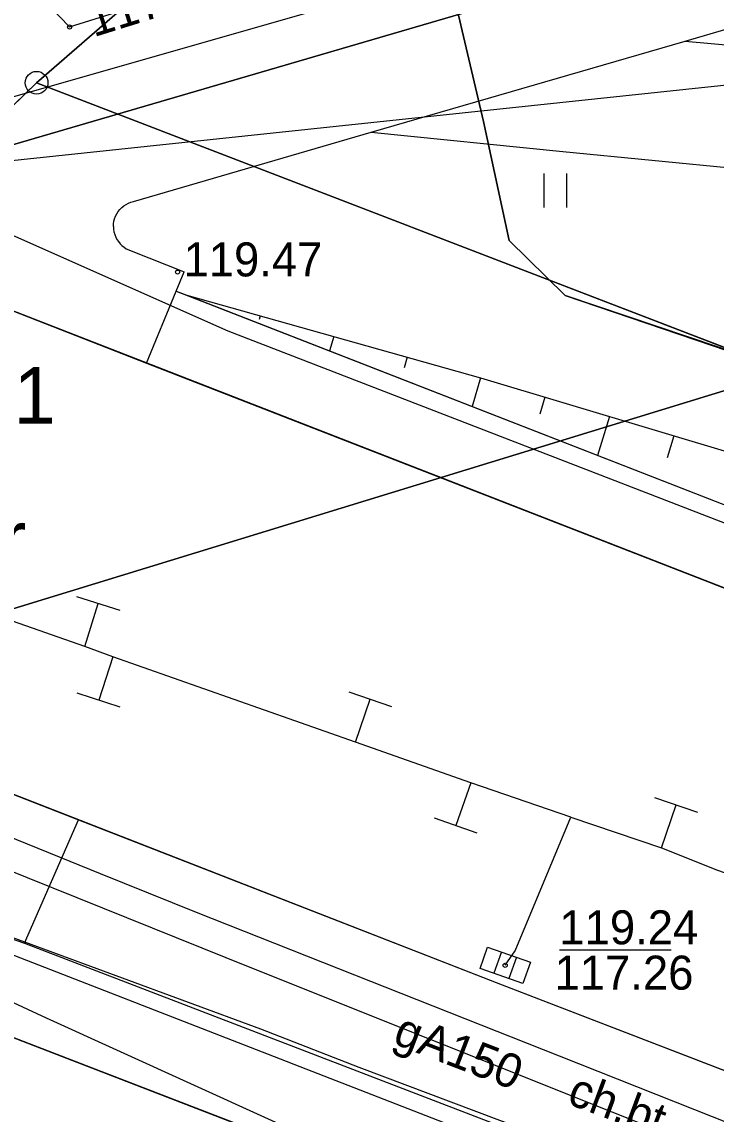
# Model space of a CAD drawing. Extents: x 6432121 to 6432331, y 5662538 to 5662686.
# Drawn here: x 6432164.01 to 6432179.34, y 5662599.43 to 5662623.53 of the extents above; entities that cross this region are included whole.
import ezdxf

# ---------------------------------------------------------------- set-up
doc = ezdxf.new("R2010")
doc.units = 0
for name, color, linetype in [('Warstwa 1', 7, 'Continuous'), ('Warstwa 10', 7, 'Continuous'), ('Warstwa 12', 7, 'Continuous'), ('Warstwa 13', 7, 'Continuous'), ('Warstwa 14', 7, 'Continuous'), ('Warstwa 15', 7, 'Continuous'), ('Warstwa 19', 7, 'Continuous'), ('Warstwa 2', 7, 'Continuous'), ('Warstwa 20', 7, 'Continuous'), ('Warstwa 21', 7, 'Continuous'), ('Warstwa 25', 7, 'Continuous'), ('Warstwa 4', 7, 'Continuous'), ('Warstwa 5', 7, 'Continuous'), ('Warstwa 6', 7, 'Continuous'), ('Warstwa 8', 7, 'Continuous'), ('Warstwa 9', 7, 'Continuous')]:
    doc.layers.add(name, color=color, linetype=linetype)

msp = doc.modelspace()

# ---------------------------------------------------------------- linework, layer by layer
at = {"layer": 'Warstwa 1'}
for p, q in [((6432164.332, 5662622.19), (6432166.394, 5662623.975)), ((6432164.332, 5662622.19), (6432166.394, 5662623.975)), ((6432147.05, 5662605.45), (6432164.332, 5662622.19)), ((6432147.05, 5662605.45), (6432164.332, 5662622.19)), ((6432164.332, 5662622.19), (6432180.9, 5662615.82)), ((6432164.332, 5662622.19), (6432180.9, 5662615.82)), ((6432147.05, 5662605.45), (6432180.9, 5662615.82)), ((6432147.05, 5662605.45), (6432180.9, 5662615.82)), ((6432155.186, 5662604.45), (6432246.621, 5662569.177)), ((6432155.186, 5662604.45), (6432246.621, 5662569.177))]:
    msp.add_line(p, q, dxfattribs=at)
at = {"layer": 'Warstwa 10'}
for p, q in [((6432167.648, 5662617.501), (6432174.135, 5662615.678)), ((6432167.648, 5662617.501), (6432210.732, 5662600.706)), ((6432169.27, 5662617.045), (6432169.248, 5662616.966)), ((6432170.892, 5662616.59), (6432170.802, 5662616.272)), ((6432172.514, 5662616.134), (6432172.446, 5662615.896)), ((6432174.135, 5662615.678), (6432173.951, 5662615.044)), ((6432174.135, 5662615.678), (6432199.73, 5662608.02)), ((6432175.557, 5662615.253), (6432175.446, 5662614.878)), ((6432176.979, 5662614.828), (6432176.72, 5662613.965)), ((6432178.401, 5662614.402), (6432178.254, 5662613.913))]:
    msp.add_line(p, q, dxfattribs=at)
msp.add_circle((6432164.332, 5662622.19), 0.25, dxfattribs=at)
at = {"layer": 'Warstwa 12'}
for points in [[(6432151.934, 5662659.962), (6432163.647, 5662662.364), (6432165.031, 5662661.271), (6432166.026, 5662656.887), (6432167.998, 5662648.227), (6432170.198, 5662638.637), (6432172.215, 5662629.789), (6432174.2, 5662621.336), (6432174.764, 5662618.709), (6432176.004, 5662617.499), (6432181.388, 5662615.664), (6432187.493, 5662613.63), (6432194.563, 5662611.29), (6432209.024, 5662605.561), (6432218.668, 5662601.72), (6432230.17, 5662597.186), (6432236.4, 5662594.702), (6432238.551, 5662593.742), (6432242.89, 5662591.993), (6432244.915, 5662591.158), (6432249.823, 5662589.199), (6432255.518, 5662586.99), (6432264.175, 5662583.483)], [(6432246.73, 5662630.84), (6432246.66, 5662631.45), (6432245.74, 5662640.67), (6432245.267, 5662641.347), (6432244.6, 5662641.33), (6432196.62, 5662630.41), (6432162.36, 5662620.4), (6432161.76, 5662619.96), (6432161.08, 5662620.39), (6432144.64, 5662638.75), (6432139.05, 5662643.99), (6432134.66, 5662649.12), (6432133.76, 5662650.98), (6432133.196, 5662651.358)], [(6432157.15, 5662630.3), (6432157.97, 5662630.56), (6432158.44, 5662630.26), (6432165.06, 5662623.42), (6432193.45, 5662632.27), (6432200.21, 5662630.55), (6432202.99, 5662631.34), (6432212.51, 5662634.26), (6432214.29, 5662637.14), (6432238.97, 5662644.59), (6432245.32, 5662646.8), (6432246.36, 5662647.14)], [(6432161.76, 5662619.96), (6432162.36, 5662620.4), (6432196.62, 5662630.41), (6432244.6, 5662641.33), (6432245.267, 5662641.347)], [(6432156.818, 5662630.202), (6432158.039, 5662625.384), (6432159.105, 5662620.911), (6432168.554, 5662616.714), (6432182.01, 5662611.519), (6432201.034, 5662604.23), (6432217.284, 5662598.028), (6432236.124, 5662590.737), (6432242.639, 5662588.267), (6432252.12, 5662584.559), (6432258.988, 5662581.806), (6432263.17, 5662580.184), (6432269.496, 5662577.686)], [(6432244.915, 5662591.158), (6432242.89, 5662591.993), (6432238.551, 5662593.742), (6432237.475, 5662594.222), (6432236.4, 5662594.702), (6432230.17, 5662597.186), (6432224.419, 5662599.453), (6432218.668, 5662601.72), (6432209.024, 5662605.561), (6432194.563, 5662611.29), (6432187.493, 5662613.63), (6432176.004, 5662617.499), (6432174.764, 5662618.709), (6432174.2, 5662621.336), (6432172.215, 5662629.789)], [(6432249.05, 5662629.25), (6432248.64, 5662629.45), (6432162.596, 5662620.344), (6432161.76, 5662619.96)], [(6432210.104, 5662582.327), (6432202.024, 5662585.528), (6432196.52, 5662587.717), (6432191.249, 5662589.791), (6432189.37, 5662590.565), (6432183.794, 5662592.014), (6432184.035, 5662592.662), (6432182.021, 5662593.597), (6432173.569, 5662597.514), (6432171.087, 5662598.578), (6432164.548, 5662601.548), (6432162.154, 5662602.662), (6432161.25, 5662603.009), (6432157.524, 5662604.493), (6432155.401, 5662604.519), (6432154.521, 5662606.358), (6432156.966, 5662612.242), (6432159.458, 5662618.215), (6432160.518, 5662620.909), (6432160.428, 5662620.978), (6432157.66, 5662622.108), (6432158.701, 5662622.869), (6432165.926, 5662625.245)], [(6432127.185, 5662618.897), (6432135.629, 5662615.848), (6432142.79, 5662613.281), (6432154.997, 5662608.849), (6432160.46, 5662606.879), (6432165.736, 5662604.745), (6432167.852, 5662603.89), (6432175.869, 5662600.716), (6432188.607, 5662595.673), (6432197.141, 5662592.258), (6432208.285, 5662587.853), (6432217.328, 5662584.25), (6432226.269, 5662580.703), (6432229.116, 5662579.575), (6432234.631, 5662577.404), (6432234.076, 5662575.247), (6432232.817, 5662570.334), (6432230.472, 5662561.671), (6432228.926, 5662556.053)], [(6432228.367, 5662556.053), (6432231.658, 5662568.249), (6432233.96, 5662576.659), (6432221.597, 5662581.652), (6432210.31, 5662586.256), (6432196.752, 5662591.605), (6432184.96, 5662596.314), (6432169.081, 5662602.651), (6432160.264, 5662606.196), (6432148.936, 5662610.33), (6432147.827, 5662610.792), (6432135.842, 5662615.166), (6432127.959, 5662618.065)], [(6432127.946, 5662615.962), (6432128.842, 5662616.521), (6432129.879, 5662616.161), (6432135.004, 5662614.244), (6432137.96, 5662613.1), (6432142.879, 5662611.278), (6432154.141, 5662607.021), (6432159.281, 5662605.095), (6432161.845, 5662604.079), (6432162.876, 5662603.668), (6432169.279, 5662601.311), (6432171.448, 5662600.465), (6432177.657, 5662598.132), (6432182.74, 5662596.197), (6432190.963, 5662593.097), (6432191.954, 5662592.706)], [(6432176.128, 5662605.986), (6432173.923, 5662606.743), (6432171.375, 5662607.643), (6432166.013, 5662609.519), (6432165.395, 5662609.747), (6432160.301, 5662611.534), (6432159.028, 5662611.977)], [(6432125.976, 5662559.881), (6432127.22, 5662563.81), (6432133.93, 5662584.09), (6432142.61, 5662608.19), (6432143.204, 5662608.85), (6432144.41, 5662608.72), (6432156.66, 5662605.17), (6432161.55, 5662603.82), (6432185, 5662594.71), (6432189.43, 5662592.42), (6432210.16, 5662585.32), (6432215.53, 5662583.54), (6432216.154, 5662583.288)], [(6432174.679, 5662602.716), (6432174.901, 5662603.034), (6432176.128, 5662605.986)], [(6432176.128, 5662605.986), (6432178.129, 5662605.31), (6432179.366, 5662604.816), (6432180.433, 5662604.439), (6432181.97, 5662603.896), (6432182.541, 5662603.695), (6432183.741, 5662603.284), (6432184.926, 5662602.88), (6432185.896, 5662602.523), (6432189.937, 5662601.037), (6432192.41, 5662600.108)]]:
    msp.add_lwpolyline(points, dxfattribs=at)
at = {"layer": 'Warstwa 14'}
msp.add_line((6432175.88, 5662603.054), (6432178.342, 5662603.054), dxfattribs=at)
for centre in [(6432165.06, 5662623.42), (6432174.679, 5662602.716), (6432174.679, 5662602.716)]:
    msp.add_circle(centre, 0.045, dxfattribs=at)
at = {"layer": 'Warstwa 19'}
for p, q in [((6432165.216, 5662610.851), (6432166.17, 5662610.552)), ((6432165.395, 5662609.747), (6432165.693, 5662610.702)), ((6432166.013, 5662609.519), (6432165.704, 5662608.568)), ((6432166.179, 5662608.413), (6432165.228, 5662608.723)), ((6432171.224, 5662608.751), (6432172.17, 5662608.429)), ((6432171.375, 5662607.643), (6432171.697, 5662608.59)), ((6432173.923, 5662606.743), (6432173.591, 5662605.8)), ((6432177.978, 5662606.418), (6432178.925, 5662606.095)), ((6432178.129, 5662605.31), (6432178.452, 5662606.257)), ((6432174.063, 5662605.634), (6432173.119, 5662605.966))]:
    msp.add_line(p, q, dxfattribs=at)
at = {"layer": 'Warstwa 20'}
for p, q in [((6432167.648, 5662617.501), (6432174.135, 5662615.678)), ((6432174.135, 5662615.678), (6432199.73, 5662608.02))]:
    msp.add_line(p, q, dxfattribs=at)
at = {"layer": 'Warstwa 21'}
msp.add_line((6432167.648, 5662617.501), (6432210.732, 5662600.706), dxfattribs=at)
at = {"layer": 'Warstwa 25'}
msp.add_circle((6432167.444, 5662618.013), 0.045, dxfattribs=at)
at = {"layer": 'Warstwa 4'}
for p, q in [((6432174.598, 5662603.01), (6432174.43, 5662602.539)), ((6432174.928, 5662602.893), (6432174.76, 5662602.422))]:
    msp.add_line(p, q, dxfattribs=at)
msp.add_lwpolyline([(6432174.291, 5662603.119), (6432175.234, 5662602.784), (6432175.067, 5662602.313), (6432174.124, 5662602.648)], close=True, dxfattribs=at)
at = {"layer": 'Warstwa 5'}
for p, q in [((6432178.65, 5662623.11), (6432179.89, 5662623.47)), ((6432178.65, 5662623.11), (6432183.354, 5662622.679)), ((6432166.47, 5662619.57), (6432171.721, 5662621.096)), ((6432171.721, 5662621.096), (6432175.954, 5662620.673)), ((6432175.954, 5662620.673), (6432187.151, 5662619.575)), ((6432175.54, 5662619.44), (6432175.54, 5662620.19)), ((6432176.04, 5662619.44), (6432176.04, 5662620.19)), ((6432166.413, 5662619.554), (6432166.47, 5662619.57)), ((6432166.101, 5662619.297), (6432166.133, 5662619.347)), ((6432166.133, 5662619.347), (6432166.17, 5662619.393)), ((6432166.17, 5662619.393), (6432166.211, 5662619.435)), ((6432166.211, 5662619.435), (6432166.257, 5662619.473)), ((6432166.257, 5662619.473), (6432166.306, 5662619.505)), ((6432166.306, 5662619.505), (6432166.358, 5662619.533)), ((6432166.358, 5662619.533), (6432166.413, 5662619.554)), ((6432166.03, 5662619.074), (6432166.039, 5662619.132)), ((6432166.039, 5662619.132), (6432166.054, 5662619.189)), ((6432166.054, 5662619.189), (6432166.075, 5662619.244)), ((6432166.075, 5662619.244), (6432166.101, 5662619.297)), ((6432166.027, 5662619.015), (6432166.03, 5662619.074)), ((6432166.027, 5662619.015), (6432166.031, 5662618.956)), ((6432166.031, 5662618.956), (6432166.04, 5662618.897)), ((6432166.04, 5662618.897), (6432166.056, 5662618.84)), ((6432166.056, 5662618.84), (6432166.078, 5662618.785)), ((6432166.078, 5662618.785), (6432166.105, 5662618.733)), ((6432166.105, 5662618.733), (6432166.137, 5662618.684)), ((6432166.137, 5662618.684), (6432166.174, 5662618.638)), ((6432166.174, 5662618.638), (6432166.216, 5662618.596)), ((6432166.216, 5662618.596), (6432166.262, 5662618.559)), ((6432166.262, 5662618.559), (6432166.312, 5662618.528)), ((6432166.312, 5662618.528), (6432166.365, 5662618.501)), ((6432166.365, 5662618.501), (6432166.42, 5662618.48)), ((6432166.42, 5662618.48), (6432167.59, 5662618.02)), ((6432167.414, 5662617.592), (6432167.59, 5662618.02)), ((6432167.414, 5662617.592), (6432167.648, 5662617.501)), ((6432167.648, 5662617.501), (6432167.648, 5662617.501)), ((6432167.648, 5662617.501), (6432174.135, 5662615.678)), ((6432174.135, 5662615.678), (6432199.73, 5662608.02)), ((6432159.412, 5662604.762), (6432164.068, 5662603.207)), ((6432164.068, 5662603.207), (6432188.299, 5662593.907))]:
    msp.add_line(p, q, dxfattribs=at)
at = {"layer": 'Warstwa 6'}
for points in [[(6432234.842, 5662644.244), (6432245.39, 5662639.916), (6432244.087, 5662648.722), (6432241.262, 5662679.658), (6432232.544, 5662677.413), (6432183.398, 5662664.76), (6432164.325, 5662660.371), (6432136.954, 5662653.004), (6432141.907, 5662600.47), (6432147.05, 5662605.45), (6432164.332, 5662622.19), (6432166.394, 5662623.975)], [(6432166.394, 5662623.975), (6432164.332, 5662622.19), (6432180.9, 5662615.82), (6432193.86, 5662619.79), (6432228.29, 5662630.34), (6432246.69, 5662636.13), (6432245.39, 5662639.916), (6432234.842, 5662644.244)], [(6432164.332, 5662622.19), (6432147.05, 5662605.45), (6432180.9, 5662615.82)], [(6432180.9, 5662615.82), (6432147.05, 5662605.45), (6432141.907, 5662600.47), (6432155.186, 5662604.45), (6432246.621, 5662569.177), (6432269.007, 5662560.534), (6432263.163, 5662588.197), (6432259.074, 5662585.787)]]:
    msp.add_lwpolyline(points, close=True, dxfattribs=at)
for points in [[(6432261.892, 5662579.254), (6432260.419, 5662579.482), (6432250.699, 5662583.246), (6432245.014, 5662585.481), (6432215.968, 5662596.774), (6432192.716, 5662605.904), (6432163.326, 5662617.343), (6432161.597, 5662617.988)], [(6432159.72, 5662608.085), (6432174.611, 5662602.284), (6432189.213, 5662596.666), (6432233.139, 5662579.721)], [(6432249.006, 5662556.053), (6432246.621, 5662569.177), (6432155.186, 5662604.45), (6432141.907, 5662600.47), (6432128.788, 5662558.646), (6432132.46, 5662567.032), (6432163.983, 5662578.631), (6432172.647, 5662574.865), (6432180.454, 5662556.053)]]:
    msp.add_lwpolyline(points, dxfattribs=at)
at = {"layer": 'Warstwa 8'}
for p, q in [((6432163.326, 5662617.343), (6432192.716, 5662605.904)), ((6432159.72, 5662608.085), (6432165.26, 5662605.926)), ((6432165.26, 5662605.926), (6432174.611, 5662602.284)), ((6432174.611, 5662602.284), (6432189.213, 5662596.666))]:
    msp.add_line(p, q, dxfattribs=at)
at = {"layer": 'Warstwa 9'}
for p, q in [((6432165.54, 5662622.37), (6432179.18, 5662626.28)), ((6432165.54, 5662622.37), (6432179.18, 5662626.28)), ((6432178.65, 5662623.11), (6432179.89, 5662623.47)), ((6432171.721, 5662621.096), (6432178.65, 5662623.11)), ((6432171.721, 5662621.096), (6432178.65, 5662623.11)), ((6432178.65, 5662623.11), (6432183.354, 5662622.679)), ((6432156.916, 5662619.947), (6432165.54, 5662622.37)), ((6432156.916, 5662619.947), (6432165.54, 5662622.37)), ((6432166.47, 5662619.57), (6432171.721, 5662621.096)), ((6432171.721, 5662621.096), (6432175.954, 5662620.673)), ((6432175.954, 5662620.673), (6432187.151, 5662619.575)), ((6432166.413, 5662619.554), (6432166.47, 5662619.57)), ((6432166.101, 5662619.297), (6432166.133, 5662619.347)), ((6432166.133, 5662619.347), (6432166.17, 5662619.393)), ((6432166.17, 5662619.393), (6432166.211, 5662619.435)), ((6432166.211, 5662619.435), (6432166.257, 5662619.473)), ((6432166.257, 5662619.473), (6432166.306, 5662619.505)), ((6432166.306, 5662619.505), (6432166.358, 5662619.533)), ((6432166.358, 5662619.533), (6432166.413, 5662619.554)), ((6432166.03, 5662619.074), (6432166.039, 5662619.132)), ((6432166.039, 5662619.132), (6432166.054, 5662619.189)), ((6432166.054, 5662619.189), (6432166.075, 5662619.244)), ((6432166.075, 5662619.244), (6432166.101, 5662619.297)), ((6432166.027, 5662619.015), (6432166.03, 5662619.074)), ((6432166.027, 5662619.015), (6432166.031, 5662618.956)), ((6432166.031, 5662618.956), (6432166.04, 5662618.897)), ((6432166.04, 5662618.897), (6432166.056, 5662618.84)), ((6432166.056, 5662618.84), (6432166.078, 5662618.785)), ((6432166.078, 5662618.785), (6432166.105, 5662618.733)), ((6432166.105, 5662618.733), (6432166.137, 5662618.684)), ((6432166.137, 5662618.684), (6432166.174, 5662618.638)), ((6432166.174, 5662618.638), (6432166.216, 5662618.596)), ((6432166.216, 5662618.596), (6432166.262, 5662618.559)), ((6432166.262, 5662618.559), (6432166.312, 5662618.528)), ((6432166.312, 5662618.528), (6432166.365, 5662618.501)), ((6432166.365, 5662618.501), (6432166.42, 5662618.48)), ((6432166.42, 5662618.48), (6432167.59, 5662618.02)), ((6432167.414, 5662617.592), (6432167.59, 5662618.02)), ((6432166.761, 5662616.006), (6432167.414, 5662617.592)), ((6432166.761, 5662616.006), (6432167.414, 5662617.592)), ((6432167.414, 5662617.592), (6432189.19, 5662609.104)), ((6432163.326, 5662617.343), (6432166.761, 5662616.006)), ((6432166.761, 5662616.006), (6432192.716, 5662605.904)), ((6432159.72, 5662608.085), (6432165.26, 5662605.926)), ((6432164.068, 5662603.207), (6432165.26, 5662605.926)), ((6432164.068, 5662603.207), (6432165.26, 5662605.926)), ((6432165.26, 5662605.926), (6432174.611, 5662602.284)), ((6432159.412, 5662604.762), (6432164.068, 5662603.207)), ((6432164.068, 5662603.207), (6432188.299, 5662593.907)), ((6432174.611, 5662602.284), (6432189.213, 5662596.666))]:
    msp.add_line(p, q, dxfattribs=at)

# ---------------------------------------------------------------- texts
at = {"layer": 'Warstwa 13'}
msp.add_text('gA150', height=0.75, rotation=338.9389, dxfattribs=at).set_placement((6432172.17, 5662600.997))
at = {"layer": 'Warstwa 14'}
msp.add_text('117.77', height=0.75, rotation=17.3148, dxfattribs=at).set_placement((6432165.593, 5662623.193))
msp.add_text('117.26', height=0.75, dxfattribs=at).set_placement((6432175.768, 5662602.179))
at = {"layer": 'Warstwa 15'}
for s, height, p in [('6/1', 1.25, (6432162.432, 5662614.666)), ('119.24', 0.75, (6432175.875, 5662603.179))]:
    msp.add_text(s, height=height, dxfattribs=at).set_placement(p)
at = {"layer": 'Warstwa 2'}
msp.add_text('dr', height=1.25, dxfattribs=at).set_placement((6432162.615, 5662611.502))
at = {"layer": 'Warstwa 25'}
msp.add_text('119.47', height=0.75, dxfattribs=at).set_placement((6432167.575, 5662617.917))
at = {"layer": 'Warstwa 9'}
msp.add_text('ch.bt.', height=0.75, rotation=339.6437, dxfattribs=at).set_placement((6432176.015, 5662599.672))

doc.saveas('drawing.dxf')
